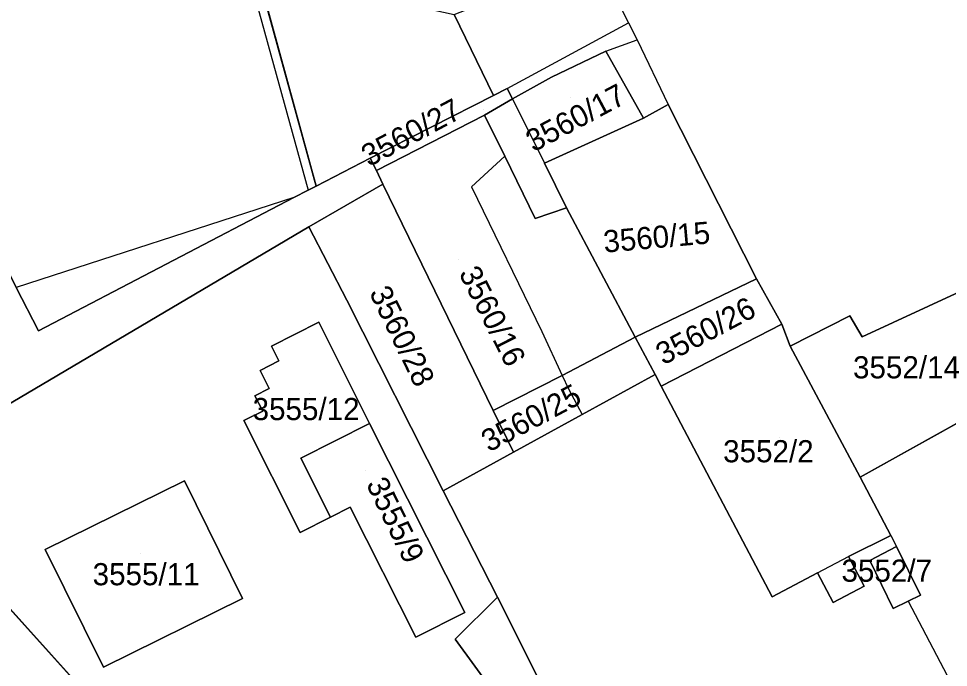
# Model space of a CAD drawing. Extents: x -262657 to -261595, y -1238015 to -1237156.
# Drawn here: x -262558.2 to -262474.2, y -1237393.1 to -1237334.5 of the extents above; entities that cross this region are included whole.
import ezdxf

# ---------------------------------------------------------------- set-up
doc = ezdxf.new("R2010")
doc.units = 0
for name, color, linetype in [('body_kn', 7, 'Continuous'), ('kladpar_druhypozemkov', 7, 'Continuous'), ('kladpar_hranice', 7, 'Continuous'), ('kladpar_parcelnecisla', 7, 'Continuous'), ('kladpar_plochy', 7, 'Continuous'), ('zappar_hrandruhpozemk', 7, 'Continuous')]:
    doc.layers.add(name, color=color, linetype=linetype)

msp = doc.modelspace()

# ---------------------------------------------------------------- linework, layer by layer
at = {"layer": 'body_kn'}
for p, q in [((-262503.11, -1237334.88), (-262503.11, -1237334.88)), ((-262503.11, -1237334.88), (-262503.11, -1237334.88)), ((-262502.32, -1237336.41), (-262502.32, -1237336.41)), ((-262505.16, -1237337.44), (-262505.16, -1237337.44)), ((-262505.16, -1237337.44), (-262505.16, -1237337.44)), ((-262510.07, -1237339.8), (-262510.07, -1237339.8)), ((-262515.3, -1237341.44), (-262515.3, -1237341.44)), ((-262514.06, -1237340.81), (-262514.06, -1237340.81)), ((-262514.06, -1237340.81), (-262514.06, -1237340.81)), ((-262513.59, -1237341.73), (-262513.59, -1237341.73)), ((-262513.59, -1237341.73), (-262513.59, -1237341.73)), ((-262499.53, -1237342.25), (-262499.53, -1237342.25)), ((-262516.11, -1237343.23), (-262516.11, -1237343.23)), ((-262501.74, -1237343.49), (-262501.74, -1237343.49)), ((-262526.44, -1237347.1), (-262526.44, -1237347.1)), ((-262526.44, -1237347.1), (-262526.44, -1237347.1)), ((-262514.28, -1237346.93), (-262514.28, -1237346.93)), ((-262514.28, -1237346.93), (-262514.28, -1237346.93)), ((-262525.89, -1237348.22), (-262525.89, -1237348.22)), ((-262510.69, -1237347.55), (-262510.69, -1237347.55)), ((-262531.33, -1237349.62), (-262531.33, -1237349.62)), ((-262525.3, -1237349.45), (-262525.3, -1237349.45)), ((-262517.28, -1237349.68), (-262517.28, -1237349.68)), ((-262533.34, -1237350.65), (-262533.34, -1237350.65)), ((-262533.34, -1237350.65), (-262533.34, -1237350.65)), ((-262532.04, -1237349.98), (-262532.04, -1237349.98)), ((-262508.7, -1237351.59), (-262508.7, -1237351.59)), ((-262508.7, -1237351.59), (-262508.7, -1237351.59)), ((-262511.55, -1237352.56), (-262511.55, -1237352.56)), ((-262531.98, -1237353.32), (-262531.98, -1237353.32)), ((-262491.55, -1237358.01), (-262491.55, -1237358.01)), ((-262491.55, -1237358.01), (-262491.55, -1237358.01)), ((-262528.57, -1237359.93), (-262528.57, -1237359.93)), ((-262483.1, -1237361.34), (-262483.1, -1237361.34)), ((-262531.09, -1237361.93), (-262531.09, -1237361.93)), ((-262489.25, -1237362.09), (-262489.25, -1237362.09)), ((-262556.43, -1237362.71), (-262556.43, -1237362.71)), ((-262510.94, -1237362.76), (-262510.94, -1237362.76)), ((-262502.51, -1237363.27), (-262502.51, -1237363.27)), ((-262502.51, -1237363.27), (-262502.51, -1237363.27)), ((-262481.99, -1237363.24), (-262481.99, -1237363.24)), ((-262535.37, -1237364.09), (-262535.37, -1237364.09)), ((-262488.5, -1237364.1), (-262488.5, -1237364.1)), ((-262534.7, -1237365.42), (-262534.7, -1237365.42)), ((-262536.4, -1237366.28), (-262536.4, -1237366.28)), ((-262509.1, -1237366.73), (-262509.1, -1237366.73)), ((-262509.1, -1237366.73), (-262509.1, -1237366.73)), ((-262500.71, -1237366.65), (-262500.71, -1237366.65)), ((-262500.71, -1237366.65), (-262500.71, -1237366.65)), ((-262535.57, -1237367.92), (-262535.57, -1237367.92)), ((-262508.54, -1237367.93), (-262508.54, -1237367.93)), ((-262500.15, -1237367.7), (-262500.15, -1237367.7)), ((-262500.15, -1237367.7), (-262500.15, -1237367.7)), ((-262536.86, -1237368.57), (-262536.86, -1237368.57)), ((-262536.16, -1237369.95), (-262536.16, -1237369.95)), ((-262515.35, -1237369.89), (-262515.35, -1237369.89)), ((-262515.35, -1237369.89), (-262515.35, -1237369.89)), ((-262537.87, -1237370.81), (-262537.87, -1237370.81)), ((-262507.3, -1237370.26), (-262507.3, -1237370.26)), ((-262526.5, -1237371.09), (-262526.5, -1237371.09)), ((-262526.5, -1237371.09), (-262526.5, -1237371.09)), ((-262532.71, -1237374.2), (-262532.71, -1237374.2)), ((-262513.51, -1237373.66), (-262513.51, -1237373.66)), ((-262513.51, -1237373.66), (-262513.51, -1237373.66)), ((-262482.17, -1237375.93), (-262482.17, -1237375.93)), ((-262482.17, -1237375.93), (-262482.17, -1237375.93)), ((-262543.24, -1237376.25), (-262543.24, -1237376.25)), ((-262519.84, -1237377.16), (-262519.84, -1237377.16)), ((-262528.25, -1237378.64), (-262528.25, -1237378.64)), ((-262530.04, -1237379.54), (-262530.04, -1237379.54)), ((-262532.77, -1237380.92), (-262532.77, -1237380.92)), ((-262479.4, -1237381.2), (-262479.4, -1237381.2)), ((-262479.4, -1237381.2), (-262479.4, -1237381.2)), ((-262555.81, -1237382.46), (-262555.81, -1237382.46)), ((-262478.9, -1237382.18), (-262478.9, -1237382.18)), ((-262483.22, -1237383.08), (-262483.22, -1237383.08)), ((-262481.3, -1237383.46), (-262481.3, -1237383.46)), ((-262481.3, -1237383.46), (-262481.3, -1237383.46)), ((-262486.03, -1237384.56), (-262486.03, -1237384.56)), ((-262486.03, -1237384.56), (-262486.03, -1237384.56)), ((-262481.8, -1237385.78), (-262481.8, -1237385.78)), ((-262537.98, -1237386.89), (-262537.98, -1237386.89)), ((-262514.95, -1237386.75), (-262514.95, -1237386.75)), ((-262490.13, -1237386.72), (-262490.13, -1237386.72)), ((-262476.73, -1237386.58), (-262476.73, -1237386.58)), ((-262484.61, -1237387.26), (-262484.61, -1237387.26)), ((-262477.83, -1237387.12), (-262477.83, -1237387.12)), ((-262477.83, -1237387.12), (-262477.83, -1237387.12)), ((-262517.9, -1237388.15), (-262517.9, -1237388.15)), ((-262479.19, -1237387.78), (-262479.19, -1237387.78)), ((-262522.33, -1237390.38), (-262522.33, -1237390.38)), ((-262522.33, -1237390.38), (-262522.33, -1237390.38)), ((-262518.77, -1237390.55), (-262518.77, -1237390.55)), ((-262550.55, -1237393.1), (-262550.55, -1237393.1)), ((-262550.55, -1237393.1), (-262550.55, -1237393.1))]:
    msp.add_line(p, q, dxfattribs=at)
at = {"layer": 'kladpar_druhypozemkov'}
for p, q in [((-262508.38, -1237341.66), (-262508.38, -1237341.66)), ((-262516.17, -1237342.72), (-262516.17, -1237342.72)), ((-262501.06, -1237353.11), (-262501.06, -1237353.11)), ((-262518.43, -1237356.29), (-262518.43, -1237356.29)), ((-262495.83, -1237361.47), (-262495.83, -1237361.47)), ((-262522.37, -1237364.16), (-262522.37, -1237364.16)), ((-262477.9, -1237364.92), (-262477.9, -1237364.92)), ((-262531.95, -1237368.41), (-262531.95, -1237368.41)), ((-262510.72, -1237369.05), (-262510.72, -1237369.05)), ((-262489.46, -1237372.38), (-262489.46, -1237372.38)), ((-262526.9, -1237375.35), (-262526.9, -1237375.35)), ((-262547.2, -1237382.79), (-262547.2, -1237382.79)), ((-262479.41, -1237383.7), (-262479.41, -1237383.7))]:
    msp.add_line(p, q, dxfattribs=at)
at = {"layer": 'kladpar_hranice'}
for p, q in [((-262429.07, -1237346.36), (-262482.17, -1237375.93)), ((-262482.17, -1237375.93), (-262429.07, -1237346.36)), ((-262491.55, -1237358.01), (-262502.51, -1237363.27)), ((-262502.51, -1237363.27), (-262491.55, -1237358.01)), ((-262479.4, -1237381.2), (-262482.17, -1237375.93))]:
    msp.add_line(p, q, dxfattribs=at)
for points in [[(-262574.37, -1237249.46), (-262568.63, -1237248.12), (-262568.05, -1237247.91), (-262567.35, -1237249.24), (-262566.74, -1237250.59), (-262564.55, -1237256.82), (-262558.85, -1237270.72), (-262552.98, -1237286.01), (-262550.94, -1237291.12), (-262542.72, -1237312.39), (-262540.2, -1237319.46), (-262538.34, -1237323.9), (-262536.56, -1237330.58), (-262531.33, -1237349.62), (-262532.04, -1237349.98), (-262533.34, -1237350.65), (-262556.43, -1237362.71), (-262558.44, -1237358.79), (-262564.27, -1237347.05)], [(-262544.97, -1237277.21), (-262547.68, -1237283.68), (-262541.83, -1237298.18), (-262537.2, -1237309.76), (-262532.89, -1237321.1), (-262529.29, -1237326.85), (-262525.82, -1237331.27), (-262522.72, -1237333.28), (-262518.85, -1237334.11), (-262515.3, -1237341.44), (-262526.44, -1237347.1), (-262531.33, -1237349.62), (-262536.56, -1237330.58), (-262538.34, -1237323.9), (-262540.2, -1237319.46), (-262542.72, -1237312.39), (-262550.94, -1237291.12), (-262552.98, -1237286.01), (-262558.85, -1237270.72), (-262564.55, -1237256.82), (-262566.74, -1237250.59)], [(-262473.2, -1237359.19), (-262481.99, -1237363.24), (-262483.1, -1237361.34), (-262488.5, -1237364.1), (-262489.25, -1237362.09), (-262491.55, -1237358.01), (-262499.53, -1237342.25), (-262501.74, -1237343.49), (-262505.16, -1237337.44), (-262510.07, -1237339.8), (-262513.59, -1237341.73), (-262514.06, -1237340.81), (-262515.3, -1237341.44), (-262518.85, -1237334.11), (-262506.56, -1237329.35), (-262505.64, -1237329.92), (-262489.43, -1237320.89), (-262484.59, -1237318.04), (-262485.02, -1237316.52), (-262470.96, -1237307.46)], [(-262508.7, -1237351.59), (-262511.55, -1237352.56), (-262514.28, -1237346.93), (-262516.11, -1237343.23), (-262513.59, -1237341.73), (-262510.07, -1237339.8), (-262505.16, -1237337.44), (-262501.74, -1237343.49), (-262510.69, -1237347.55), (-262508.7, -1237351.59)], [(-262526.44, -1237347.1), (-262515.3, -1237341.44), (-262514.06, -1237340.81), (-262513.59, -1237341.73), (-262516.11, -1237343.23), (-262525.89, -1237348.22), (-262526.44, -1237347.1)], [(-262502.51, -1237363.27), (-262508.7, -1237351.59), (-262510.69, -1237347.55), (-262501.74, -1237343.49), (-262499.53, -1237342.25), (-262491.55, -1237358.01)], [(-262515.35, -1237369.89), (-262525.3, -1237349.45), (-262525.89, -1237348.22), (-262516.11, -1237343.23), (-262514.28, -1237346.93), (-262511.55, -1237352.56), (-262508.7, -1237351.59), (-262502.51, -1237363.27), (-262509.1, -1237366.73), (-262515.35, -1237369.89)], [(-262526.44, -1237347.1), (-262525.89, -1237348.22), (-262525.3, -1237349.45), (-262531.98, -1237353.32), (-262569.17, -1237375.26), (-262573.46, -1237377.79), (-262578.97, -1237370.99), (-262577.87, -1237368.09), (-262576.44, -1237364.3), (-262576.16, -1237363.57), (-262574.21, -1237366.97), (-262562.84, -1237360.42), (-262567.03, -1237353.13), (-262573.65, -1237356.97), (-262571.33, -1237350.86), (-262568.99, -1237349.6), (-262564.27, -1237347.05), (-262558.44, -1237358.79), (-262556.43, -1237362.71), (-262533.34, -1237350.65), (-262532.04, -1237349.98), (-262531.33, -1237349.62), (-262526.44, -1237347.1)], [(-262513.51, -1237373.66), (-262519.84, -1237377.16), (-262528.57, -1237359.93), (-262531.98, -1237353.32), (-262525.3, -1237349.45), (-262515.35, -1237369.89), (-262513.51, -1237373.66)], [(-262569.17, -1237375.26), (-262531.98, -1237353.32), (-262528.57, -1237359.93), (-262519.84, -1237377.16), (-262514.95, -1237386.75)], [(-262491.55, -1237358.01), (-262489.25, -1237362.09), (-262500.15, -1237367.7)], [(-262482.17, -1237375.93), (-262488.5, -1237364.1), (-262483.1, -1237361.34), (-262481.99, -1237363.24), (-262473.2, -1237359.19)], [(-262517.9, -1237388.15), (-262526.5, -1237371.09), (-262531.09, -1237361.93), (-262535.37, -1237364.09), (-262534.7, -1237365.42), (-262536.4, -1237366.28), (-262535.57, -1237367.92), (-262536.86, -1237368.57), (-262536.16, -1237369.95), (-262537.87, -1237370.81), (-262532.77, -1237380.92), (-262530.04, -1237379.54), (-262528.25, -1237378.64), (-262522.33, -1237390.38), (-262517.9, -1237388.15)], [(-262526.5, -1237371.09), (-262532.71, -1237374.2), (-262530.04, -1237379.54), (-262532.77, -1237380.92), (-262537.87, -1237370.81), (-262536.16, -1237369.95), (-262536.86, -1237368.57), (-262535.57, -1237367.92), (-262536.4, -1237366.28), (-262534.7, -1237365.42), (-262535.37, -1237364.09), (-262531.09, -1237361.93), (-262526.5, -1237371.09)], [(-262482.17, -1237375.93), (-262479.4, -1237381.2), (-262483.22, -1237383.08), (-262481.8, -1237385.78), (-262484.61, -1237387.26), (-262486.03, -1237384.56), (-262490.13, -1237386.72), (-262500.15, -1237367.7), (-262489.25, -1237362.09), (-262488.5, -1237364.1), (-262482.17, -1237375.93)], [(-262500.71, -1237366.65), (-262507.3, -1237370.26), (-262513.51, -1237373.66), (-262515.35, -1237369.89), (-262509.1, -1237366.73), (-262502.51, -1237363.27), (-262500.71, -1237366.65)], [(-262500.15, -1237367.7), (-262500.71, -1237366.65), (-262502.51, -1237363.27)], [(-262437.9, -1237483.33), (-262449.72, -1237460.31), (-262464.28, -1237431.46), (-262469.6, -1237420.93), (-262478.29, -1237403.67), (-262478.73, -1237402.85), (-262506.09, -1237404.44), (-262514.95, -1237386.75), (-262519.84, -1237377.16), (-262513.51, -1237373.66), (-262507.3, -1237370.26), (-262500.71, -1237366.65), (-262500.15, -1237367.7), (-262490.13, -1237386.72), (-262486.03, -1237384.56), (-262484.61, -1237387.26), (-262481.8, -1237385.78), (-262483.22, -1237383.08), (-262479.4, -1237381.2)], [(-262552.09, -1237410.69), (-262573.78, -1237386.21), (-262584.43, -1237371.9), (-262578.8, -1237368.63), (-262577.87, -1237368.09), (-262578.97, -1237370.99), (-262573.46, -1237377.79), (-262569.17, -1237375.26), (-262562.79, -1237383.63), (-262550.17, -1237397.64)], [(-262522.33, -1237390.38), (-262528.25, -1237378.64), (-262530.04, -1237379.54), (-262532.71, -1237374.2), (-262526.5, -1237371.09), (-262517.9, -1237388.15), (-262522.33, -1237390.38)], [(-262514.95, -1237386.75), (-262518.77, -1237390.55), (-262501.01, -1237414.95), (-262523.77, -1237426.48), (-262550.17, -1237397.64), (-262562.79, -1237383.63), (-262569.17, -1237375.26)], [(-262550.55, -1237393.1), (-262537.98, -1237386.89), (-262543.24, -1237376.25), (-262555.81, -1237382.46), (-262550.55, -1237393.1)], [(-262550.55, -1237393.1), (-262555.81, -1237382.46), (-262543.24, -1237376.25), (-262537.98, -1237386.89), (-262550.55, -1237393.1)], [(-262481.3, -1237383.46), (-262478.9, -1237382.18), (-262476.73, -1237386.58), (-262477.83, -1237387.12), (-262479.19, -1237387.78), (-262481.3, -1237383.46)], [(-262478.9, -1237382.18), (-262481.3, -1237383.46), (-262479.19, -1237387.78), (-262477.83, -1237387.12), (-262476.73, -1237386.58), (-262478.9, -1237382.18)], [(-262478.29, -1237403.67), (-262479.33, -1237404.19), (-262493.57, -1237411.26), (-262501.01, -1237414.95), (-262518.77, -1237390.55), (-262514.95, -1237386.75), (-262506.09, -1237404.44), (-262478.73, -1237402.85), (-262478.29, -1237403.67)]]:
    msp.add_lwpolyline(points, dxfattribs=at)
at = {"layer": 'kladpar_plochy'}
for p, q in [((-262536.56, -1237330.58), (-262531.33, -1237349.62)), ((-262515.3, -1237341.44), (-262518.85, -1237334.11)), ((-262505.16, -1237337.44), (-262510.07, -1237339.8)), ((-262501.74, -1237343.49), (-262505.16, -1237337.44)), ((-262510.07, -1237339.8), (-262513.59, -1237341.73)), ((-262514.06, -1237340.81), (-262515.3, -1237341.44)), ((-262513.59, -1237341.73), (-262514.06, -1237340.81)), ((-262499.53, -1237342.25), (-262501.74, -1237343.49)), ((-262491.55, -1237358.01), (-262499.53, -1237342.25)), ((-262482.17, -1237375.93), (-262429.07, -1237346.36)), ((-262531.33, -1237349.62), (-262532.04, -1237349.98)), ((-262533.34, -1237350.65), (-262556.43, -1237362.71)), ((-262532.04, -1237349.98), (-262533.34, -1237350.65)), ((-262569.17, -1237375.26), (-262531.98, -1237353.32)), ((-262531.98, -1237353.32), (-262528.57, -1237359.93)), ((-262489.25, -1237362.09), (-262491.55, -1237358.01)), ((-262556.43, -1237362.71), (-262558.44, -1237358.79)), ((-262528.57, -1237359.93), (-262519.84, -1237377.16)), ((-262473.2, -1237359.19), (-262481.99, -1237363.24)), ((-262483.1, -1237361.34), (-262488.5, -1237364.1)), ((-262481.99, -1237363.24), (-262483.1, -1237361.34)), ((-262531.09, -1237361.93), (-262535.37, -1237364.09)), ((-262526.5, -1237371.09), (-262531.09, -1237361.93)), ((-262488.5, -1237364.1), (-262489.25, -1237362.09)), ((-262535.37, -1237364.09), (-262534.7, -1237365.42)), ((-262534.7, -1237365.42), (-262536.4, -1237366.28)), ((-262536.4, -1237366.28), (-262535.57, -1237367.92)), ((-262507.3, -1237370.26), (-262500.71, -1237366.65)), ((-262500.71, -1237366.65), (-262500.15, -1237367.7)), ((-262535.57, -1237367.92), (-262536.86, -1237368.57)), ((-262500.15, -1237367.7), (-262490.13, -1237386.72)), ((-262536.86, -1237368.57), (-262536.16, -1237369.95)), ((-262536.16, -1237369.95), (-262537.87, -1237370.81)), ((-262537.87, -1237370.81), (-262532.77, -1237380.92)), ((-262513.51, -1237373.66), (-262507.3, -1237370.26)), ((-262517.9, -1237388.15), (-262526.5, -1237371.09)), ((-262519.84, -1237377.16), (-262513.51, -1237373.66)), ((-262479.4, -1237381.2), (-262482.17, -1237375.93)), ((-262543.24, -1237376.25), (-262555.81, -1237382.46)), ((-262537.98, -1237386.89), (-262543.24, -1237376.25)), ((-262514.95, -1237386.75), (-262519.84, -1237377.16)), ((-262519.84, -1237377.16), (-262514.95, -1237386.75)), ((-262530.04, -1237379.54), (-262528.25, -1237378.64)), ((-262528.25, -1237378.64), (-262522.33, -1237390.38)), ((-262532.77, -1237380.92), (-262530.04, -1237379.54)), ((-262483.22, -1237383.08), (-262479.4, -1237381.2)), ((-262555.81, -1237382.46), (-262550.55, -1237393.1)), ((-262478.9, -1237382.18), (-262481.3, -1237383.46)), ((-262476.73, -1237386.58), (-262478.9, -1237382.18)), ((-262481.8, -1237385.78), (-262483.22, -1237383.08)), ((-262481.3, -1237383.46), (-262479.19, -1237387.78)), ((-262550.17, -1237397.64), (-262562.79, -1237383.63)), ((-262490.13, -1237386.72), (-262486.03, -1237384.56)), ((-262486.03, -1237384.56), (-262484.61, -1237387.26)), ((-262484.61, -1237387.26), (-262481.8, -1237385.78)), ((-262550.55, -1237393.1), (-262537.98, -1237386.89)), ((-262514.95, -1237386.75), (-262518.77, -1237390.55)), ((-262506.09, -1237404.44), (-262514.95, -1237386.75)), ((-262477.83, -1237387.12), (-262476.73, -1237386.58)), ((-262479.19, -1237387.78), (-262477.83, -1237387.12)), ((-262522.33, -1237390.38), (-262517.9, -1237388.15)), ((-262518.77, -1237390.55), (-262501.01, -1237414.95))]:
    msp.add_line(p, q, dxfattribs=at)
for points in [[(-262563.3, -1237255.68), (-262556.86, -1237260.6), (-262550.52, -1237263.55), (-262546.64, -1237272.98), (-262544.97, -1237277.21), (-262547.68, -1237283.68), (-262541.83, -1237298.18), (-262537.2, -1237309.76), (-262532.89, -1237321.1), (-262529.29, -1237326.85), (-262525.82, -1237331.27), (-262522.72, -1237333.28), (-262518.85, -1237334.11), (-262515.3, -1237341.44), (-262526.44, -1237347.1), (-262531.33, -1237349.62), (-262536.56, -1237330.58), (-262538.34, -1237323.9), (-262540.2, -1237319.46), (-262542.72, -1237312.39), (-262550.94, -1237291.12), (-262552.98, -1237286.01), (-262558.85, -1237270.72)], [(-262552.09, -1237410.69), (-262573.78, -1237386.21), (-262584.43, -1237371.9), (-262578.8, -1237368.63), (-262577.87, -1237368.09), (-262578.97, -1237370.99), (-262573.46, -1237377.79), (-262569.17, -1237375.26), (-262562.79, -1237383.63), (-262550.17, -1237397.64)]]:
    msp.add_lwpolyline(points, dxfattribs=at)
for points in [[(-262508.7, -1237351.59), (-262511.55, -1237352.56), (-262514.28, -1237346.93), (-262516.11, -1237343.23), (-262513.59, -1237341.73), (-262510.07, -1237339.8), (-262505.16, -1237337.44), (-262501.74, -1237343.49), (-262510.69, -1237347.55)], [(-262526.44, -1237347.1), (-262515.3, -1237341.44), (-262514.06, -1237340.81), (-262513.59, -1237341.73), (-262516.11, -1237343.23), (-262525.89, -1237348.22)], [(-262502.51, -1237363.27), (-262508.7, -1237351.59), (-262510.69, -1237347.55), (-262501.74, -1237343.49), (-262499.53, -1237342.25), (-262491.55, -1237358.01)], [(-262515.35, -1237369.89), (-262525.3, -1237349.45), (-262525.89, -1237348.22), (-262516.11, -1237343.23), (-262514.28, -1237346.93), (-262511.55, -1237352.56), (-262508.7, -1237351.59), (-262502.51, -1237363.27), (-262509.1, -1237366.73)], [(-262473.2, -1237359.19), (-262469.69, -1237366.58), (-262429.07, -1237346.36), (-262482.17, -1237375.93), (-262488.5, -1237364.1), (-262483.1, -1237361.34), (-262481.99, -1237363.24)], [(-262526.44, -1237347.1), (-262525.89, -1237348.22), (-262525.3, -1237349.45), (-262531.98, -1237353.32), (-262569.17, -1237375.26), (-262573.46, -1237377.79), (-262578.97, -1237370.99), (-262577.87, -1237368.09), (-262576.44, -1237364.3), (-262576.16, -1237363.57), (-262574.21, -1237366.97), (-262562.84, -1237360.42), (-262567.03, -1237353.13), (-262573.65, -1237356.97), (-262571.33, -1237350.86), (-262568.99, -1237349.6), (-262564.27, -1237347.05), (-262558.44, -1237358.79), (-262556.43, -1237362.71), (-262533.34, -1237350.65), (-262532.04, -1237349.98), (-262531.33, -1237349.62)], [(-262513.51, -1237373.66), (-262519.84, -1237377.16), (-262528.57, -1237359.93), (-262531.98, -1237353.32), (-262525.3, -1237349.45), (-262515.35, -1237369.89)], [(-262500.15, -1237367.7), (-262500.71, -1237366.65), (-262502.51, -1237363.27), (-262491.55, -1237358.01), (-262489.25, -1237362.09)], [(-262526.5, -1237371.09), (-262532.71, -1237374.2), (-262530.04, -1237379.54), (-262532.77, -1237380.92), (-262537.87, -1237370.81), (-262536.16, -1237369.95), (-262536.86, -1237368.57), (-262535.57, -1237367.92), (-262536.4, -1237366.28), (-262534.7, -1237365.42), (-262535.37, -1237364.09), (-262531.09, -1237361.93)], [(-262482.17, -1237375.93), (-262479.4, -1237381.2), (-262483.22, -1237383.08), (-262481.8, -1237385.78), (-262484.61, -1237387.26), (-262486.03, -1237384.56), (-262490.13, -1237386.72), (-262500.15, -1237367.7), (-262489.25, -1237362.09), (-262488.5, -1237364.1)], [(-262500.71, -1237366.65), (-262507.3, -1237370.26), (-262513.51, -1237373.66), (-262515.35, -1237369.89), (-262509.1, -1237366.73), (-262502.51, -1237363.27)], [(-262522.33, -1237390.38), (-262528.25, -1237378.64), (-262530.04, -1237379.54), (-262532.71, -1237374.2), (-262526.5, -1237371.09), (-262517.9, -1237388.15)], [(-262550.55, -1237393.1), (-262555.81, -1237382.46), (-262543.24, -1237376.25), (-262537.98, -1237386.89)], [(-262481.3, -1237383.46), (-262478.9, -1237382.18), (-262476.73, -1237386.58), (-262477.83, -1237387.12), (-262479.19, -1237387.78)], [(-262478.29, -1237403.67), (-262479.33, -1237404.19), (-262493.57, -1237411.26), (-262501.01, -1237414.95), (-262518.77, -1237390.55), (-262514.95, -1237386.75), (-262506.09, -1237404.44), (-262478.73, -1237402.85)]]:
    msp.add_lwpolyline(points, close=True, dxfattribs=at)
at = {"layer": 'zappar_hrandruhpozemk'}
for p, q in [((-262505.64, -1237329.92), (-262503.11, -1237334.88)), ((-262514.06, -1237340.81), (-262503.11, -1237334.88)), ((-262505.16, -1237337.44), (-262502.32, -1237336.41)), ((-262513.59, -1237341.73), (-262510.69, -1237347.55)), ((-262514.28, -1237346.93), (-262517.28, -1237349.68)), ((-262533.34, -1237350.65), (-262558.44, -1237358.79)), ((-262509.1, -1237366.73), (-262508.54, -1237367.93)), ((-262508.54, -1237367.93), (-262507.3, -1237370.26)), ((-262479.4, -1237381.2), (-262478.9, -1237382.18)), ((-262486.03, -1237384.56), (-262483.22, -1237383.08)), ((-262477.83, -1237387.12), (-262473.37, -1237395.61))]:
    msp.add_line(p, q, dxfattribs=at)
for points in [[(-262544.72, -1237309.65), (-262539.37, -1237323.43), (-262532.04, -1237349.98)], [(-262503.11, -1237334.88), (-262502.32, -1237336.41), (-262499.53, -1237342.25)], [(-262517.28, -1237349.68), (-262510.94, -1237362.76), (-262509.1, -1237366.73)]]:
    msp.add_lwpolyline(points, dxfattribs=at)

# ---------------------------------------------------------------- texts
at = {"layer": 'kladpar_parcelnecisla'}
for s, rotation, p in [('3560/17', 28, (-262511.692, -1237346.595)), ('3560/27', 28, (-262526.56, -1237347.928)), ('3560/15', 5, (-262505.288, -1237355.645)), ('3560/16', 297, (-262518.481, -1237357.497)), ('3560/28', 296, (-262526.572, -1237359.251)), ('3560/26', 28, (-262499.952, -1237365.84)), ('3560/25', 28, (-262515.721, -1237373.706)), ('3555/9', 296, (-262526.852, -1237376.539))]:
    msp.add_text(s, height=2, rotation=rotation, dxfattribs=at).set_placement(p)
for s, p in [('3552/14', (-262482.821, -1237367)), ('3555/12', (-262537.076, -1237370.77)), ('3552/2', (-262494.556, -1237374.58)), ('3552/7', (-262483.862, -1237385.37)), ('3555/11', (-262551.53, -1237385.69))]:
    msp.add_text(s, height=2, dxfattribs=at).set_placement(p)

doc.saveas('drawing.dxf')
